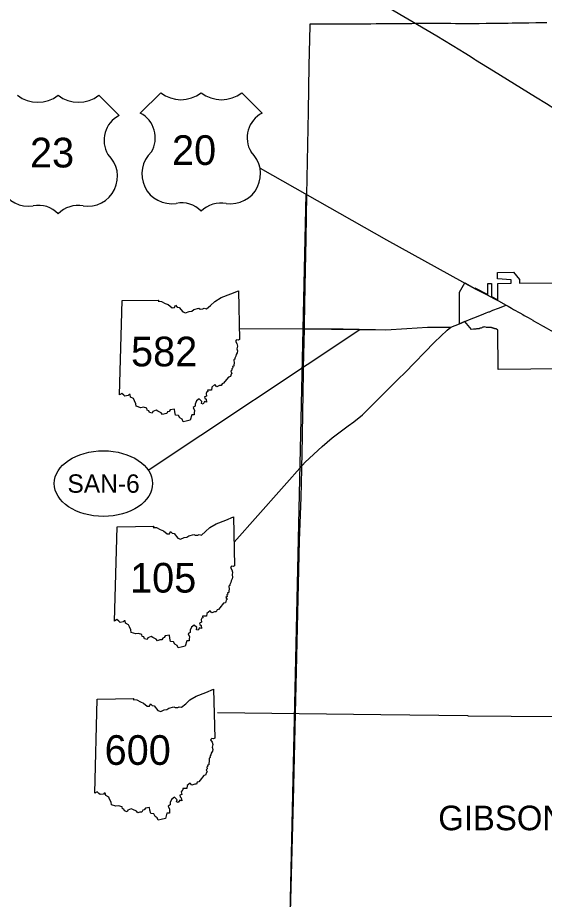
# Model space of a CAD drawing. Extents: x 0 to 798, y 0 to 440.
# Drawn here: x 124.4 to 204.7, y 218.5 to 353 of the extents above; entities that cross this region are included whole.
import ezdxf

# ---------------------------------------------------------------- set-up
doc = ezdxf.new("R2010")
doc.units = 0
for name, color, linetype in [('DV_X_Corp_Line', 7, 'Continuous'), ('GM_X_Corporation_Text', 7, 'Continuous'), ('GM_X_County', 7, 'Continuous'), ('GM_X_Interstate_Route', 7, 'Continuous'), ('GM_X_State_Route', 7, 'Continuous'), ('GM_X_US_Route', 7, 'Continuous'), ('PV_P_Text', 7, 'Continuous'), ('SH_Data', 7, 'Continuous'), ('SH_Text', 7, 'Continuous')]:
    doc.layers.add(name, color=color, linetype=linetype)

msp = doc.modelspace()

# ---------------------------------------------------------------- linework, layer by layer
at = {"layer": 'DV_X_Corp_Line'}
msp.add_lwpolyline([(207.63, 299.43), (197.63, 299.32), (197.61, 305.36), (197.58, 305.4), (197.51, 305.45), (197.45, 305.47), (197.38, 305.5), (197.37, 305.5), (197.32, 305.53), (197.27, 305.55), (197.21, 305.55), (197.14, 305.55), (197.1, 305.56), (197.08, 305.57), (197.01, 305.59), (196.96, 305.62), (196.89, 305.64), (196.83, 305.65), (196.77, 305.67), (196.7, 305.71), (196.64, 305.73), (196.59, 305.73), (196.46, 305.75), (196.2, 305.75), (196.06, 305.76), (195.88, 305.74), (195.59, 305.83), (195.46, 305.81), (195.33, 305.77), (195.23, 305.73), (195.15, 305.68), (195.04, 305.64), (194.97, 305.62), (194.92, 305.61), (194.76, 305.54), (194.67, 305.52), (194.44, 305.51), (194.35, 305.51), (194.24, 305.5), (194.14, 305.49), (194, 305.48), (193.88, 305.46), (193.56, 305.43), (192.58, 306.65), (191.75, 306.32), (191.75, 311.11), (192.55, 312.55), (194.09, 311.68), (194.09, 311.79), (196.08, 310.76), (196.06, 312.44), (196.64, 312.46), (196.63, 310.47), (197.61, 309.94), (197.61, 312.47), (199.64, 312.49), (199.63, 313.03), (197.56, 313.17), (197.53, 314.14), (199.99, 314.2), (200.88, 313.06), (200.89, 312.52), (210.92, 312.58)], dxfattribs=at)
at = {"layer": 'GM_X_County'}
msp.add_lwpolyline([(165.72, 207.1), (166.07, 220.3), (166.42, 233.58), (166.59, 240.18), (166.74, 246.85), (166.89, 253.32), (167.04, 259.97), (167.19, 266.56), (167.34, 273.24), (167.58, 279.79), (167.6, 280.25), (167.64, 281.5), (167.7, 284.62), (167.73, 286.31), (167.97, 298.85), (167.98, 299.59), (168.09, 305.53), (168.1, 306.13), (168.21, 312.02), (168.35, 319.26), (168.48, 325.99), (168.71, 338.66), (168.84, 345.68), (168.95, 351.77), (168.97, 352.06), (169.75, 352.05), (170.35, 352.05), (171.74, 352.05), (172.51, 352.04), (173.14, 352.05), (173.53, 352.05), (174.27, 352.06), (175.13, 352.06), (175.8, 352.07), (176.48, 352.07), (177.4, 352.08), (178.22, 352.08), (179.06, 352.09), (180.21, 352.1), (180.65, 352.1), (180.81, 352.1), (180.9, 352.09), (180.95, 352.09), (181.12, 352.09), (181.65, 352.1), (182.84, 352.11), (183.5, 352.12), (183.82, 352.12), (184.25, 352.13), (184.48, 352.13), (184.77, 352.14), (185.05, 352.14), (185.15, 352.14), (185.37, 352.15), (185.7, 352.15), (186.35, 352.15), (187.03, 352.15), (187.73, 352.15), (189.36, 352.15), (190.43, 352.14), (191.13, 352.13), (191.69, 352.13), (193.39, 352.13), (194.13, 352.13), (194.2, 352.13), (194.29, 352.13), (194.74, 352.13), (195.81, 352.14), (196.39, 352.15), (197.98, 352.16), (199.17, 352.18), (199.78, 352.19), (200.49, 352.19), (201.51, 352.21), (202.32, 352.22), (203.4, 352.24), (203.92, 352.25), (204.53, 352.26), (205.06, 352.27)], dxfattribs=at)
at = {"layer": 'GM_X_Interstate_Route'}
msp.add_lwpolyline([(169.37, 361.38), (188.31, 350.22), (191.79, 348.07), (192.46, 347.66), (193.36, 347.1), (194.03, 346.68), (194.19, 346.58), (196.95, 344.88), (203.35, 340.92), (205.03, 339.88), (205.6, 339.54), (206.05, 339.26), (207.28, 338.49), (208.21, 337.92), (210.55, 336.46), (216.7, 332.66), (218.5, 331.55), (220.95, 329.93)], dxfattribs=at)
at = {"layer": 'GM_X_State_Route'}
for points in [[(162.95, 122.07), (165.72, 207.1), (168.38, 326.05)], [(193.54, 307.04), (193.93, 307.19), (195.1, 307.66), (195.83, 307.95), (196.08, 308.05), (196.08, 308.05)], [(196.08, 308.05), (196.25, 308.11), (196.32, 308.14), (196.32, 308.14)], [(196.32, 308.14), (196.86, 308.36), (197.7, 308.69), (198.85, 309.15)], [(191.73, 306.32), (192.58, 306.65), (192.58, 306.65)], [(192.58, 306.65), (193.54, 307.04), (193.54, 307.04)], [(157.36, 273.01), (168.21, 285.19), (170.79, 287.57), (172.31, 288.93), (174.76, 290.73), (175.61, 291.35), (176.94, 292.44), (178.51, 293.98), (180.47, 295.94), (182.47, 297.89), (183.42, 298.8), (187.95, 303.48), (189.87, 305.32), (190.41, 305.79), (191.73, 306.32)], [(158.16, 305.56), (174.01, 305.51), (178.95, 305.44), (180.54, 305.4), (183.72, 305.58), (186.89, 305.77), (190.41, 305.79)], [(154.85, 247), (179.74, 246.68), (193.01, 246.54), (193.04, 246.5), (206.24, 246.39), (206.24, 246.39)]]:
    msp.add_lwpolyline(points, dxfattribs=at)
at = {"layer": 'GM_X_US_Route'}
for points in [[(161.34, 330.03), (180.64, 319.12), (194.16, 311.64)], [(194.16, 311.64), (195.97, 310.7), (197.01, 310.15), (197.09, 310.12), (197.68, 309.79), (197.69, 309.79)], [(197.69, 309.79), (198.85, 309.15)], [(198.85, 309.15), (199.16, 308.98), (199.67, 308.69)], [(199.67, 308.69), (200.01, 308.49), (200.96, 307.96), (201.42, 307.7), (201.63, 307.58)], [(201.63, 307.58), (202.23, 307.24), (202.95, 306.83), (202.96, 306.82)], [(202.96, 306.82), (203.7, 306.41), (204.42, 306)], [(204.42, 306), (204.49, 305.96), (204.97, 305.69), (206.04, 305.1), (207.44, 304.32), (207.46, 304.31)]]:
    msp.add_lwpolyline(points, dxfattribs=at)
at = {"layer": 'PV_P_Text'}
for p, q in [((139.83, 338.05), (136.72, 341.16)), ((139.83, 338.05), (136.72, 341.16)), ((146.18, 341.55), (143.07, 338.44)), ((146.18, 341.55), (143.07, 338.44)), ((161.65, 338.44), (158.54, 341.55)), ((161.65, 338.44), (158.54, 341.55)), ((139.9, 295.47), (140.3, 309.83)), ((139.9, 295.47), (140.3, 309.83)), ((139.14, 260.96), (139.54, 275.32)), ((139.14, 260.96), (139.54, 275.32)), ((136.11, 234.68), (136.51, 249.05)), ((136.11, 234.68), (136.51, 249.05))]:
    msp.add_line(p, q, dxfattribs=at)
for points in [[(140.3, 309.83), (145.87, 309.93), (145.78, 309.75), (146.31, 309.72), (146.87, 309.41), (147.34, 309.22), (147.92, 308.76), (148.26, 308.77), (148.41, 309.14), (148.67, 308.85), (148.99, 308.8), (149.53, 308.11), (149.98, 307.96), (150.52, 308.2), (150.92, 308.24), (151.21, 308.47), (151.98, 308.67), (152.19, 308.55), (152.6, 308.57), (152.8, 308.66), (153.15, 308.58), (153.77, 309.11), (154.41, 309.72), (155.4, 310.3), (156.87, 310.85), (158.03, 311.35), (158.2, 303.89)], [(140.3, 309.83), (145.87, 309.93), (145.78, 309.75), (146.31, 309.72), (146.87, 309.41), (147.34, 309.22), (147.92, 308.76), (148.26, 308.77), (148.41, 309.14), (148.67, 308.85), (148.99, 308.8), (149.53, 308.11), (149.98, 307.96), (150.52, 308.2), (150.92, 308.24), (151.21, 308.47), (151.98, 308.67), (152.19, 308.55), (152.6, 308.57), (152.8, 308.66), (153.15, 308.58), (153.77, 309.11), (154.41, 309.72), (155.4, 310.3), (156.87, 310.85), (158.03, 311.35), (158.2, 303.89)], [(158.2, 303.89), (158.03, 303.79), (157.76, 303.84), (157.58, 303.63), (157.8, 303.28), (157.91, 302.91), (157.81, 302.5), (157.91, 302.17), (157.84, 301.89), (157.68, 301.61), (157.62, 301.34), (157.47, 301.06), (157.49, 300.91), (157.35, 300.78), (157.38, 300.32), (157.31, 300.06), (157.33, 299.84), (157.11, 299.78), (157.16, 299.59), (157.02, 299.45), (157.05, 299.21), (156.89, 299.05), (157.05, 298.74), (156.92, 298.64), (156.82, 298.26), (156.54, 298.18), (155.97, 297.48), (155.77, 297.22), (155.54, 297.16), (155.42, 296.89), (155.14, 296.89), (154.72, 296.7), (154.45, 297.02), (153.98, 296.63), (153.93, 296.18), (153.33, 296.2), (153.35, 295.97), (153.22, 295.91), (153.09, 295.68), (153.16, 295.28), (152.88, 295.17), (152.92, 294.94), (153.1, 294.8), (153.18, 294.35), (152.88, 294.44), (152.63, 294.06), (152.38, 294.15), (152.47, 294.47), (152.04, 294.86), (151.64, 294.55), (151.43, 294.06), (151.43, 293.73), (151.13, 293.53), (151.32, 293.06), (151.29, 292.74), (151.29, 292.43), (150.92, 292.44), (150.69, 291.62)], [(158.2, 303.89), (158.03, 303.79), (157.76, 303.84), (157.58, 303.63), (157.8, 303.28), (157.91, 302.91), (157.81, 302.5), (157.91, 302.17), (157.84, 301.89), (157.68, 301.61), (157.62, 301.34), (157.47, 301.06), (157.49, 300.91), (157.35, 300.78), (157.38, 300.32), (157.31, 300.06), (157.33, 299.84), (157.11, 299.78), (157.16, 299.59), (157.02, 299.45), (157.05, 299.21), (156.89, 299.05), (157.05, 298.74), (156.92, 298.64), (156.82, 298.26), (156.54, 298.18), (155.97, 297.48), (155.77, 297.22), (155.54, 297.16), (155.42, 296.89), (155.14, 296.89), (154.72, 296.7), (154.45, 297.02), (153.98, 296.63), (153.93, 296.18), (153.33, 296.2), (153.35, 295.97), (153.22, 295.91), (153.09, 295.68), (153.16, 295.28), (152.88, 295.17), (152.92, 294.94), (153.1, 294.8), (153.18, 294.35), (152.88, 294.44), (152.63, 294.06), (152.38, 294.15), (152.47, 294.47), (152.04, 294.86), (151.64, 294.55), (151.43, 294.06), (151.43, 293.73), (151.13, 293.53), (151.32, 293.06), (151.29, 292.74), (151.29, 292.43), (150.92, 292.44), (150.69, 291.62)], [(150.69, 291.62), (150.04, 291.46), (149.59, 291.37), (149.43, 291.74), (149.11, 291.94), (148.9, 292.31), (148.43, 292.37), (148.32, 292.88), (148.27, 293.3), (147.64, 293.2), (147.46, 292.94), (147.24, 292.87), (147.11, 292.62), (146.8, 292.59), (146.47, 292.47), (146.26, 292.73), (145.72, 292.98), (145.48, 293.11), (144.97, 292.91), (144.86, 292.67), (144.46, 292.77), (144.36, 293.04), (144.12, 293.12), (144.07, 293.41), (143.55, 293.56), (143.15, 293.5), (142.44, 293.73), (142.4, 294.11), (142.16, 294.57), (142.04, 294.89), (141.59, 295.13), (141.5, 295.51), (141.36, 295.5), (141.23, 295.34), (140.73, 295.27), (140.54, 295.43), (140.26, 295.69), (139.9, 295.47)], [(150.69, 291.62), (150.04, 291.46), (149.59, 291.37), (149.43, 291.74), (149.11, 291.94), (148.9, 292.31), (148.43, 292.37), (148.32, 292.88), (148.27, 293.3), (147.64, 293.2), (147.46, 292.94), (147.24, 292.87), (147.11, 292.62), (146.8, 292.59), (146.47, 292.47), (146.26, 292.73), (145.72, 292.98), (145.48, 293.11), (144.97, 292.91), (144.86, 292.67), (144.46, 292.77), (144.36, 293.04), (144.12, 293.12), (144.07, 293.41), (143.55, 293.56), (143.15, 293.5), (142.44, 293.73), (142.4, 294.11), (142.16, 294.57), (142.04, 294.89), (141.59, 295.13), (141.5, 295.51), (141.36, 295.5), (141.23, 295.34), (140.73, 295.27), (140.54, 295.43), (140.26, 295.69), (139.9, 295.47)], [(139.54, 275.32), (145.11, 275.42), (145.02, 275.24), (145.55, 275.21), (146.11, 274.9), (146.58, 274.71), (147.16, 274.25), (147.5, 274.26), (147.65, 274.63), (147.92, 274.34), (148.23, 274.29), (148.77, 273.6), (149.22, 273.45), (149.76, 273.69), (150.16, 273.73), (150.45, 273.96), (151.22, 274.16), (151.43, 274.04), (151.84, 274.06), (152.04, 274.15), (152.39, 274.07), (153.01, 274.6), (153.65, 275.21), (154.64, 275.79), (156.11, 276.34), (157.27, 276.84), (157.44, 269.38)], [(139.54, 275.32), (145.11, 275.42), (145.02, 275.24), (145.55, 275.21), (146.11, 274.9), (146.58, 274.71), (147.16, 274.25), (147.5, 274.26), (147.65, 274.63), (147.92, 274.34), (148.23, 274.29), (148.77, 273.6), (149.22, 273.45), (149.76, 273.69), (150.16, 273.73), (150.45, 273.96), (151.22, 274.16), (151.43, 274.04), (151.84, 274.06), (152.04, 274.15), (152.39, 274.07), (153.01, 274.6), (153.65, 275.21), (154.64, 275.79), (156.11, 276.34), (157.27, 276.84), (157.44, 269.38)], [(157.44, 269.38), (157.27, 269.28), (157, 269.33), (156.82, 269.12), (157.04, 268.77), (157.15, 268.4), (157.06, 267.99), (157.15, 267.66), (157.08, 267.38), (156.92, 267.1), (156.86, 266.83), (156.72, 266.55), (156.73, 266.4), (156.59, 266.27), (156.62, 265.81), (156.55, 265.55), (156.57, 265.33), (156.35, 265.27), (156.4, 265.08), (156.26, 264.94), (156.29, 264.7), (156.13, 264.54), (156.29, 264.23), (156.16, 264.13), (156.06, 263.75), (155.78, 263.67), (155.21, 262.98), (155.01, 262.71), (154.78, 262.65), (154.66, 262.38), (154.38, 262.38), (153.97, 262.19), (153.7, 262.51), (153.22, 262.12), (153.17, 261.68), (152.57, 261.69), (152.59, 261.46), (152.46, 261.4), (152.33, 261.17), (152.41, 260.77), (152.12, 260.66), (152.16, 260.43), (152.34, 260.29), (152.42, 259.84), (152.12, 259.93), (151.88, 259.55), (151.62, 259.64), (151.71, 259.96), (151.28, 260.35), (150.88, 260.04), (150.67, 259.55), (150.67, 259.22), (150.37, 259.02), (150.56, 258.55), (150.53, 258.23), (150.53, 257.92), (150.16, 257.93), (149.93, 257.11)], [(157.44, 269.38), (157.27, 269.28), (157, 269.33), (156.82, 269.12), (157.04, 268.77), (157.15, 268.4), (157.06, 267.99), (157.15, 267.66), (157.08, 267.38), (156.92, 267.1), (156.86, 266.83), (156.72, 266.55), (156.73, 266.4), (156.59, 266.27), (156.62, 265.81), (156.55, 265.55), (156.57, 265.33), (156.35, 265.27), (156.4, 265.08), (156.26, 264.94), (156.29, 264.7), (156.13, 264.54), (156.29, 264.23), (156.16, 264.13), (156.06, 263.75), (155.78, 263.67), (155.21, 262.98), (155.01, 262.71), (154.78, 262.65), (154.66, 262.38), (154.38, 262.38), (153.97, 262.19), (153.7, 262.51), (153.22, 262.12), (153.17, 261.68), (152.57, 261.69), (152.59, 261.46), (152.46, 261.4), (152.33, 261.17), (152.41, 260.77), (152.12, 260.66), (152.16, 260.43), (152.34, 260.29), (152.42, 259.84), (152.12, 259.93), (151.88, 259.55), (151.62, 259.64), (151.71, 259.96), (151.28, 260.35), (150.88, 260.04), (150.67, 259.55), (150.67, 259.22), (150.37, 259.02), (150.56, 258.55), (150.53, 258.23), (150.53, 257.92), (150.16, 257.93), (149.93, 257.11)], [(149.93, 257.11), (149.28, 256.95), (148.83, 256.86), (148.67, 257.23), (148.35, 257.43), (148.14, 257.81), (147.67, 257.86), (147.56, 258.37), (147.51, 258.79), (146.88, 258.69), (146.7, 258.43), (146.48, 258.36), (146.35, 258.11), (146.04, 258.08), (145.71, 257.96), (145.5, 258.22), (144.96, 258.47), (144.72, 258.6), (144.21, 258.4), (144.1, 258.16), (143.7, 258.26), (143.61, 258.53), (143.36, 258.61), (143.31, 258.9), (142.79, 259.05), (142.39, 258.99), (141.68, 259.22), (141.64, 259.6), (141.4, 260.06), (141.28, 260.38), (140.83, 260.62), (140.74, 261), (140.6, 260.99), (140.47, 260.83), (139.98, 260.76), (139.78, 260.92), (139.5, 261.18), (139.14, 260.96)], [(149.93, 257.11), (149.28, 256.95), (148.83, 256.86), (148.67, 257.23), (148.35, 257.43), (148.14, 257.81), (147.67, 257.86), (147.56, 258.37), (147.51, 258.79), (146.88, 258.69), (146.7, 258.43), (146.48, 258.36), (146.35, 258.11), (146.04, 258.08), (145.71, 257.96), (145.5, 258.22), (144.96, 258.47), (144.72, 258.6), (144.21, 258.4), (144.1, 258.16), (143.7, 258.26), (143.61, 258.53), (143.36, 258.61), (143.31, 258.9), (142.79, 259.05), (142.39, 258.99), (141.68, 259.22), (141.64, 259.6), (141.4, 260.06), (141.28, 260.38), (140.83, 260.62), (140.74, 261), (140.6, 260.99), (140.47, 260.83), (139.98, 260.76), (139.78, 260.92), (139.5, 261.18), (139.14, 260.96)], [(136.51, 249.05), (142.08, 249.14), (142, 248.97), (142.52, 248.93), (143.08, 248.62), (143.55, 248.43), (144.13, 247.97), (144.48, 247.98), (144.62, 248.35), (144.89, 248.06), (145.2, 248.01), (145.75, 247.33), (146.19, 247.18), (146.73, 247.41), (147.13, 247.45), (147.43, 247.68), (148.19, 247.88), (148.4, 247.76), (148.81, 247.79), (149.01, 247.88), (149.37, 247.8), (149.99, 248.32), (150.63, 248.93), (151.61, 249.52), (153.08, 250.07), (154.24, 250.56), (154.41, 243.11)], [(136.51, 249.05), (142.08, 249.14), (142, 248.97), (142.52, 248.93), (143.08, 248.62), (143.55, 248.43), (144.13, 247.97), (144.48, 247.98), (144.62, 248.35), (144.89, 248.06), (145.2, 248.01), (145.75, 247.33), (146.19, 247.18), (146.73, 247.41), (147.13, 247.45), (147.43, 247.68), (148.19, 247.88), (148.4, 247.76), (148.81, 247.79), (149.01, 247.88), (149.37, 247.8), (149.99, 248.32), (150.63, 248.93), (151.61, 249.52), (153.08, 250.07), (154.24, 250.56), (154.41, 243.11)], [(154.41, 243.11), (154.24, 243), (153.97, 243.05), (153.79, 242.84), (154.02, 242.49), (154.12, 242.12), (154.03, 241.72), (154.12, 241.38), (154.06, 241.1), (153.89, 240.82), (153.83, 240.56), (153.69, 240.28), (153.7, 240.12), (153.56, 240), (153.59, 239.53), (153.52, 239.27), (153.54, 239.05), (153.32, 238.99), (153.37, 238.81), (153.23, 238.66), (153.26, 238.42), (153.1, 238.26), (153.26, 237.95), (153.14, 237.85), (153.03, 237.47), (152.75, 237.39), (152.18, 236.7), (151.98, 236.43), (151.76, 236.37), (151.63, 236.1), (151.36, 236.1), (150.94, 235.91), (150.67, 236.23), (150.19, 235.85), (150.14, 235.4), (149.54, 235.41), (149.56, 235.19), (149.43, 235.12), (149.31, 234.89), (149.38, 234.49), (149.1, 234.39), (149.13, 234.15), (149.31, 234.01), (149.39, 233.56), (149.09, 233.65), (148.85, 233.28), (148.6, 233.36), (148.68, 233.68), (148.26, 234.07), (147.85, 233.76), (147.64, 233.27), (147.64, 232.94), (147.34, 232.74), (147.53, 232.27), (147.5, 231.95), (147.51, 231.64), (147.13, 231.65), (146.9, 230.83)], [(154.41, 243.11), (154.24, 243), (153.97, 243.05), (153.79, 242.84), (154.02, 242.49), (154.12, 242.12), (154.03, 241.72), (154.12, 241.38), (154.06, 241.1), (153.89, 240.82), (153.83, 240.56), (153.69, 240.28), (153.7, 240.12), (153.56, 240), (153.59, 239.53), (153.52, 239.27), (153.54, 239.05), (153.32, 238.99), (153.37, 238.81), (153.23, 238.66), (153.26, 238.42), (153.1, 238.26), (153.26, 237.95), (153.14, 237.85), (153.03, 237.47), (152.75, 237.39), (152.18, 236.7), (151.98, 236.43), (151.76, 236.37), (151.63, 236.1), (151.36, 236.1), (150.94, 235.91), (150.67, 236.23), (150.19, 235.85), (150.14, 235.4), (149.54, 235.41), (149.56, 235.19), (149.43, 235.12), (149.31, 234.89), (149.38, 234.49), (149.1, 234.39), (149.13, 234.15), (149.31, 234.01), (149.39, 233.56), (149.09, 233.65), (148.85, 233.28), (148.6, 233.36), (148.68, 233.68), (148.26, 234.07), (147.85, 233.76), (147.64, 233.27), (147.64, 232.94), (147.34, 232.74), (147.53, 232.27), (147.5, 231.95), (147.51, 231.64), (147.13, 231.65), (146.9, 230.83)], [(146.9, 230.83), (146.25, 230.67), (145.8, 230.58), (145.64, 230.95), (145.32, 231.15), (145.11, 231.53), (144.65, 231.58), (144.54, 232.1), (144.49, 232.52), (143.85, 232.41), (143.68, 232.16), (143.45, 232.09), (143.32, 231.83), (143.02, 231.81), (142.69, 231.68), (142.47, 231.94), (141.93, 232.19), (141.69, 232.33), (141.18, 232.12), (141.08, 231.88), (140.67, 231.99), (140.58, 232.26), (140.34, 232.34), (140.28, 232.62), (139.76, 232.77), (139.36, 232.71), (138.66, 232.94), (138.61, 233.32), (138.38, 233.78), (138.25, 234.1), (137.81, 234.34), (137.72, 234.72), (137.57, 234.71), (137.44, 234.55), (136.95, 234.48), (136.75, 234.64), (136.48, 234.9), (136.11, 234.68)], [(146.9, 230.83), (146.25, 230.67), (145.8, 230.58), (145.64, 230.95), (145.32, 231.15), (145.11, 231.53), (144.65, 231.58), (144.54, 232.1), (144.49, 232.52), (143.85, 232.41), (143.68, 232.16), (143.45, 232.09), (143.32, 231.83), (143.02, 231.81), (142.69, 231.68), (142.47, 231.94), (141.93, 232.19), (141.69, 232.33), (141.18, 232.12), (141.08, 231.88), (140.67, 231.99), (140.58, 232.26), (140.34, 232.34), (140.28, 232.62), (139.76, 232.77), (139.36, 232.71), (138.66, 232.94), (138.61, 233.32), (138.38, 233.78), (138.25, 234.1), (137.81, 234.34), (137.72, 234.72), (137.57, 234.71), (137.44, 234.55), (136.95, 234.48), (136.75, 234.64), (136.48, 234.9), (136.11, 234.68)]]:
    msp.add_lwpolyline(points, dxfattribs=at)
for centre, radius, start, end in [((127.45, 345.09), 5, 231.813, 308.187), ((127.45, 345.09), 5, 231.813, 308.187), ((133.63, 345.09), 5, 231.813, 308.187), ((133.63, 345.09), 5, 231.813, 308.187), ((149.27, 345.48), 5, 231.813, 308.187), ((149.27, 345.48), 5, 231.813, 308.187), ((155.45, 345.48), 5, 231.813, 308.187), ((155.45, 345.48), 5, 231.813, 308.187), ((141.77, 334.3), 4.23, 117.3892, 210.8825), ((141.77, 334.3), 4.23, 117.3892, 210.8825), ((141.12, 334.68), 4.23, 329.1175, 62.6108), ((141.12, 334.68), 4.23, 329.1175, 62.6108), ((163.59, 334.68), 4.23, 117.3892, 210.8825), ((163.59, 334.68), 4.23, 117.3892, 210.8825), ((147.86, 329.18), 4.56, 133.0046, 278.7282), ((147.86, 329.18), 4.56, 133.0046, 278.7282), ((156.85, 329.18), 4.56, 261.2718, 46.9954), ((156.85, 329.18), 4.56, 261.2718, 46.9954), ((126.04, 328.79), 4.56, 133.0046, 278.7282), ((126.04, 328.79), 4.56, 133.0046, 278.7282), ((135.03, 328.79), 4.56, 261.2718, 46.9954), ((135.03, 328.79), 4.56, 261.2718, 46.9954), ((127.57, 320.29), 4.08, 43.4177, 101.8742), ((127.57, 320.29), 4.08, 43.4177, 101.8742), ((133.59, 320.02), 4.33, 79.9613, 134.7468), ((133.59, 320.02), 4.33, 79.9613, 134.7468), ((149.39, 320.68), 4.08, 43.4177, 101.8742), ((149.39, 320.68), 4.08, 43.4177, 101.8742), ((155.41, 320.4), 4.33, 79.9613, 134.7468), ((155.41, 320.4), 4.33, 79.9613, 134.7468)]:
    msp.add_arc(centre, radius, start, end, dxfattribs=at)
at = {"layer": 'SH_Data'}
msp.add_line((144.29, 283.96), (176.56, 305.44), dxfattribs=at)
msp.add_ellipse((137.44, 281.93), major_axis=(7.5, 0), ratio=0.666667, dxfattribs=at)
at = {"layer": 'SH_Text'}
msp.add_lwpolyline([(168.09, 305.53), (180.54, 305.4), (183.72, 305.58), (186.89, 305.77), (190.41, 305.79)], dxfattribs=at)

# ---------------------------------------------------------------- texts
at = {"layer": 'GM_X_Corporation_Text'}
msp.add_text('GIBSONBURG', height=3.75, rotation=0, dxfattribs=at).set_placement((188.51, 229.05))
at = {"layer": 'PV_P_Text'}
for s, p in [('20', (147.9, 330.53)), ('23', (126.24, 330.15)), ('582', (141.65, 299.81)), ('105', (141.5, 265.3)), ('600', (137.62, 239.02))]:
    msp.add_text(s, height=4.528, dxfattribs=at).set_placement(p)
at = {"layer": 'SH_Data'}
msp.add_text('SAN-6', height=2.8, dxfattribs=at).set_placement((131.95, 280.53))

doc.saveas('drawing.dxf')
